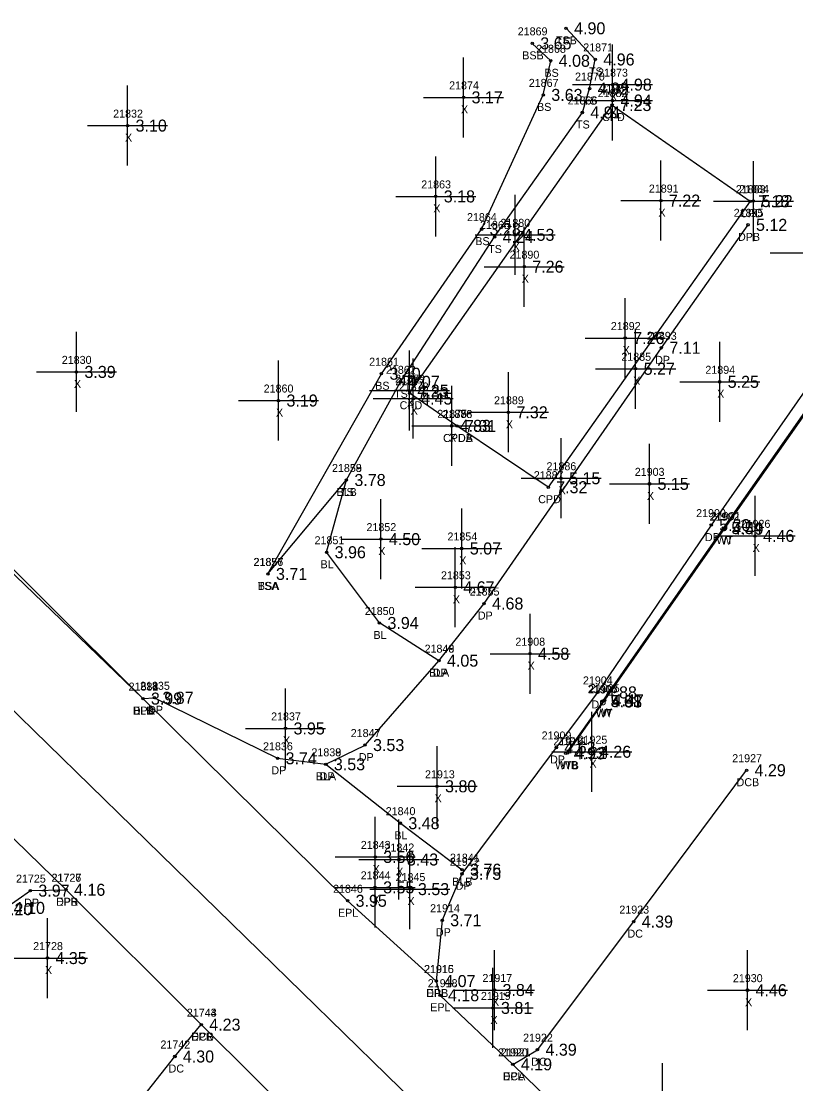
# Model space of a CAD drawing. Extents: x 2608745 to 2610333, y 641917 to 643463.
# Drawn here: x 2610174 to 2610270.8, y 642017.3 to 642150.1 of the extents above; entities that cross this region are included whole.
import ezdxf

# ---------------------------------------------------------------- set-up
doc = ezdxf.new("R2010")
doc.units = 0
for name, color, linetype in [('RD_DTM_BkLn1', 7, 'Continuous'), ('RD_DTM_BkLn2', 7, 'Continuous'), ('RD_DTM_BkLn_txCode', 7, 'Continuous'), ('RD_EX_BldgApp', 7, 'Continuous'), ('RD_EX_Conc', 7, 'Continuous'), ('RD_EX_Conc_txCode', 7, 'Continuous'), ('RD_EX_Driveway', 7, 'Continuous'), ('RD_EX_Driveway_txCode', 7, 'Continuous'), ('RD_EX_Misc', 7, 'Continuous'), ('RD_EX_Misc_txCode', 7, 'Continuous'), ('RD_EX_Road', 7, 'Continuous'), ('RD_EX_Road_txCode', 7, 'Continuous'), ('RD_EX_TX_Conc_ELEV', 7, 'Continuous'), ('RD_EX_TX_Driveway_ELEV', 7, 'Continuous'), ('RD_EX_TX_Misc_ELEV', 7, 'Continuous'), ('RD_EX_TX_Road_ELEV', 7, 'Continuous'), ('RD_SMD_Locator', 7, 'Continuous')]:
    doc.layers.add(name, color=color, linetype=linetype)

msp = doc.modelspace()

# ---------------------------------------------------------------- linework, layer by layer
at = {"layer": 'RD_DTM_BkLn1'}
for points in [[(2609568.4, 642647.43), (2609618.95, 642597.92), (2609693.89, 642525.38), (2609771.33, 642450.27), (2609850.26, 642373.69), (2609929.54, 642297.24), (2610000.01, 642230.49), (2610078.71, 642154.75), (2610156.09, 642080.44), (2610235.53, 642002.94), (2610263.59, 641975.77)], [(2609627.58, 642607.09), (2609630.23, 642605.37), (2609646.31, 642589.45), (2609703.16, 642535.02), (2609781.51, 642459.84), (2609859.44, 642383.51), (2609938.95, 642307.03), (2610008.76, 642239.49), (2610086.74, 642162.99), (2610105.31, 642145.89), (2610105.31, 642145.89), (2610140.26, 642113.1), (2610153.89, 642100.28), (2610164.72, 642089.82), (2610189.2, 642065.46)], [(2610226.2, 642070.2), (2610218.76, 642074.91), (2610212.16, 642083.75), (2610214.63, 642092.78)], [(2610212.06, 642057.25), (2610221.37, 642049.89), (2610229.08, 642044.08)]]:
    msp.add_lwpolyline(points, dxfattribs=at)
at = {"layer": 'RD_DTM_BkLn2'}
for points in [[(2610204.83, 642081.04), (2610214.63, 642092.78), (2610221.39, 642105.05), (2610233.15, 642123.15), (2610244.12, 642138.71), (2610245.03, 642141.7), (2610245.74, 642145.34), (2610242.09, 642149.23)], [(2610204.83, 642081.04), (2610219.01, 642106.06), (2610231.52, 642124.13), (2610239.24, 642140.91), (2610240.16, 642145.17), (2610237.86, 642147.35)], [(2610282.65, 642116.6), (2610261.73, 642086.77), (2610246.64, 642065.15), (2610246.68, 642065.1), (2610242.04, 642058.61)]]:
    msp.add_lwpolyline(points, dxfattribs=at)
at = {"layer": 'RD_EX_BldgApp'}
msp.add_lwpolyline([(2610282.97, 642116.74), (2610261.85, 642086.69), (2610246.9, 642065.25), (2610242.27, 642058.67)], dxfattribs=at)
at = {"layer": 'RD_EX_Conc'}
for points in [[(2610228.45, 642099.53), (2610222.53, 642103.62), (2610247.84, 642139.64), (2610265.09, 642127.62), (2610239.85, 642091.88), (2610228.45, 642099.53)], [(2610235.43, 642019.75), (2610238.51, 642021.58), (2610250.54, 642037.59), (2610264.64, 642056.51)], [(2610175.78, 641998.66), (2610183.75, 642008.74), (2610193.19, 642020.73), (2610196.49, 642024.71)]]:
    msp.add_lwpolyline(points, dxfattribs=at)
at = {"layer": 'RD_EX_Driveway'}
for points in [[(2610189.2, 642065.46), (2610190.63, 642065.56), (2610206.03, 642058), (2610212.06, 642057.25), (2610216.96, 642059.65), (2610226.2, 642070.2), (2610231.84, 642077.34), (2610253.99, 642109.3), (2610264.82, 642124.67)], [(2610280.77, 642116.6), (2610260.22, 642087.14), (2610246.03, 642066.23), (2610240.86, 642059.35), (2610229.07, 642043.56), (2610226.6, 642037.76), (2610225.86, 642030.16)], [(2610165.14, 642055.61), (2610164.87, 642054.53), (2610164.15, 642051.63), (2610160.61, 642047.27), (2610170.48, 642039.14), (2610172.05, 642039.3), (2610175.13, 642041.46), (2610179.59, 642041.57)]]:
    msp.add_lwpolyline(points, dxfattribs=at)
at = {"layer": 'RD_EX_Misc'}
for p, q in [((2610247.89, 642137.19), (2610247.89, 642147.19)), ((2610229.27, 642135.6), (2610229.27, 642145.6)), ((2610247.89, 642135.2), (2610247.89, 642145.2)), ((2610187.28, 642132.07), (2610187.28, 642142.07)), ((2610242.89, 642142.19), (2610252.89, 642142.19)), ((2610224.27, 642140.6), (2610234.27, 642140.6)), ((2610242.89, 642140.2), (2610252.89, 642140.2)), ((2610182.28, 642137.07), (2610192.28, 642137.07)), ((2610225.8, 642123.22), (2610225.8, 642133.22)), ((2610253.94, 642122.7), (2610253.94, 642132.7)), ((2610265.5, 642122.64), (2610265.5, 642132.64)), ((2610220.8, 642128.22), (2610230.8, 642128.22)), ((2610235.72, 642118.42), (2610235.72, 642128.42)), ((2610248.94, 642127.7), (2610258.94, 642127.7)), ((2610260.5, 642127.64), (2610270.5, 642127.64)), ((2610236.86, 642114.44), (2610236.86, 642124.44)), ((2610230.72, 642123.42), (2610240.72, 642123.42)), ((2610267.61, 642121.16), (2610277.61, 642121.16)), ((2610231.86, 642119.44), (2610241.86, 642119.44)), ((2610249.47, 642105.52), (2610249.47, 642115.52)), ((2610180.89, 642101.29), (2610180.89, 642111.29)), ((2610250.78, 642101.68), (2610250.78, 642111.68)), ((2610244.47, 642110.52), (2610254.47, 642110.52)), ((2610261.28, 642100.05), (2610261.28, 642110.05)), ((2610222.5, 642098.95), (2610222.5, 642108.95)), ((2610206.14, 642097.71), (2610206.14, 642107.71)), ((2610222.97, 642097.96), (2610222.97, 642107.96)), ((2610175.89, 642106.29), (2610185.89, 642106.29)), ((2610234.88, 642096.24), (2610234.88, 642106.24)), ((2610245.78, 642106.68), (2610255.78, 642106.68)), ((2610227.79, 642094.55), (2610227.79, 642104.55)), ((2610256.28, 642105.05), (2610266.28, 642105.05)), ((2610217.5, 642103.95), (2610227.5, 642103.95)), ((2610217.97, 642102.96), (2610227.97, 642102.96)), ((2610201.14, 642102.71), (2610211.14, 642102.71)), ((2610229.88, 642101.24), (2610239.88, 642101.24)), ((2610222.79, 642099.55), (2610232.79, 642099.55)), ((2610241.46, 642088), (2610241.46, 642098)), ((2610252.51, 642087.3), (2610252.51, 642097.3)), ((2610236.46, 642093), (2610246.46, 642093)), ((2610247.51, 642092.3), (2610257.51, 642092.3)), ((2610218.94, 642080.39), (2610218.94, 642090.39)), ((2610265.71, 642080.8), (2610265.71, 642090.8)), ((2610229.05, 642079.22), (2610229.05, 642089.22)), ((2610260.71, 642085.8), (2610270.71, 642085.8)), ((2610213.94, 642085.39), (2610223.94, 642085.39)), ((2610224.05, 642084.22), (2610234.05, 642084.22)), ((2610228.24, 642074.37), (2610228.24, 642084.37)), ((2610223.24, 642079.37), (2610233.24, 642079.37)), ((2610237.58, 642066.07), (2610237.58, 642076.07)), ((2610232.58, 642071.07), (2610242.58, 642071.07)), ((2610207.02, 642056.73), (2610207.02, 642066.73)), ((2610245.32, 642053.82), (2610245.32, 642063.82)), ((2610202.02, 642061.73), (2610212.02, 642061.73)), ((2610225.96, 642049.5), (2610225.96, 642059.5)), ((2610240.32, 642058.82), (2610250.32, 642058.82)), ((2610220.96, 642054.5), (2610230.96, 642054.5)), ((2610218.23, 642040.67), (2610218.23, 642050.67)), ((2610221.19, 642040.35), (2610221.19, 642050.35)), ((2610218.22, 642036.87), (2610218.22, 642046.87)), ((2610222.57, 642036.65), (2610222.57, 642046.65)), ((2610213.23, 642045.67), (2610223.23, 642045.67)), ((2610216.19, 642045.35), (2610226.19, 642045.35)), ((2610213.22, 642041.87), (2610223.22, 642041.87)), ((2610217.57, 642041.65), (2610227.57, 642041.65)), ((2610177.27, 642028.03), (2610177.27, 642038.03)), ((2610233.14, 642024.04), (2610233.14, 642034.04)), ((2610264.76, 642024.02), (2610264.76, 642034.02)), ((2610172.27, 642033.03), (2610182.27, 642033.03)), ((2610232.95, 642021.8), (2610232.95, 642031.8)), ((2610228.14, 642029.04), (2610238.14, 642029.04)), ((2610259.76, 642029.02), (2610269.76, 642029.02)), ((2610227.95, 642026.8), (2610237.95, 642026.8)), ((2610254.14, 642009.9), (2610254.14, 642019.9))]:
    msp.add_line(p, q, dxfattribs=at)
at = {"layer": 'RD_EX_Road'}
for points in [[(2609576.61, 642656.06), (2609590.88, 642642.24), (2609605.19, 642628.78), (2609627.58, 642607.09), (2609646.03, 642589.11), (2609702.18, 642534.04), (2609780.35, 642458.95), (2609858.79, 642382.83), (2609938.32, 642306.42), (2610008.62, 642239.32), (2610086.3, 642162.54), (2610164.18, 642089.49), (2610189.2, 642065.46), (2610214.78, 642040.19), (2610225.86, 642030.16), (2610226.32, 642028.39), (2610235.43, 642019.75), (2610260.23, 641995.63), (2610272.39, 641983.25)], [(2609841.8, 642365.54), (2609898.22, 642311.07), (2609921.04, 642289.43), (2609962.12, 642250.55), (2609969.04, 642244.08), (2609979.13, 642234.19), (2609992.4, 642221.66), (2610004.86, 642210.01), (2610027, 642188.8), (2610067.64, 642149.14), (2610070.8, 642146.19), (2610073.96, 642143.05), (2610116.51, 642103.01), (2610119.68, 642100.06), (2610135.09, 642085.92), (2610148.33, 642073.03), (2610165.14, 642055.61), (2610179.59, 642041.57), (2610196.49, 642024.71), (2610209.86, 642011.42), (2610228.39, 641994.06), (2610252.93, 641970.08), (2610256.35, 641966.74)]]:
    msp.add_lwpolyline(points, dxfattribs=at)
at = {"layer": 'RD_SMD_Locator'}
for centre in [(2610242.09, 642149.23), (2610237.86, 642147.35), (2610240.16, 642145.17), (2610245.74, 642145.34), (2610245.03, 642141.7), (2610247.89, 642142.19), (2610229.27, 642140.6), (2610239.24, 642140.91), (2610247.89, 642140.2), (2610244.12, 642138.71), (2610247.84, 642139.64), (2610187.28, 642137.07), (2610225.8, 642128.22), (2610253.94, 642127.7), (2610265.09, 642127.62), (2610265.5, 642127.64), (2610231.52, 642124.13), (2610264.82, 642124.67), (2610233.15, 642123.15), (2610235.72, 642123.42), (2610236.86, 642119.44), (2610249.47, 642110.52), (2610253.99, 642109.3), (2610250.78, 642106.68), (2610180.89, 642106.29), (2610219.01, 642106.06), (2610221.39, 642105.05), (2610261.28, 642105.05), (2610206.14, 642102.71), (2610222.5, 642103.95), (2610222.53, 642103.62), (2610222.97, 642102.96), (2610234.88, 642101.24), (2610227.79, 642099.55), (2610228.45, 642099.53), (2610228.45, 642099.53), (2610214.63, 642092.78), (2610214.63, 642092.78), (2610241.46, 642093), (2610252.51, 642092.3), (2610239.85, 642091.88), (2610260.22, 642087.14), (2610261.73, 642086.77), (2610218.94, 642085.39), (2610261.85, 642086.69), (2610265.71, 642085.8), (2610229.05, 642084.22), (2610212.16, 642083.75), (2610204.83, 642081.04), (2610204.83, 642081.04), (2610228.24, 642079.37), (2610231.84, 642077.34), (2610218.76, 642074.91), (2610237.58, 642071.07), (2610226.2, 642070.2), (2610226.2, 642070.2), (2610189.2, 642065.46), (2610189.2, 642065.46), (2610189.2, 642065.46), (2610190.63, 642065.56), (2610246.03, 642066.23), (2610246.64, 642065.15), (2610246.68, 642065.1), (2610246.9, 642065.25), (2610207.02, 642061.73), (2610216.96, 642059.65), (2610240.86, 642059.35), (2610245.32, 642058.82), (2610206.03, 642058), (2610242.04, 642058.61), (2610242.27, 642058.67), (2610212.06, 642057.25), (2610212.06, 642057.25), (2610264.64, 642056.51), (2610225.96, 642054.5), (2610221.37, 642049.89), (2610218.23, 642045.67), (2610221.19, 642045.35), (2610229.07, 642043.56), (2610229.08, 642044.08), (2610179.59, 642041.57), (2610179.59, 642041.57), (2610218.22, 642041.87), (2610222.57, 642041.65), (2610175.13, 642041.46), (2610214.78, 642040.19), (2610226.6, 642037.76), (2610250.54, 642037.59), (2610177.27, 642033.03), (2610225.86, 642030.16), (2610225.86, 642030.16), (2610226.32, 642028.39), (2610233.14, 642029.04), (2610264.76, 642029.02), (2610232.95, 642026.8), (2610196.49, 642024.71), (2610196.49, 642024.71), (2610193.19, 642020.73), (2610238.51, 642021.58), (2610235.43, 642019.75), (2610235.43, 642019.75)]:
    msp.add_circle(centre, 0.15, dxfattribs=at)

# ---------------------------------------------------------------- texts
at = {"layer": 'RD_DTM_BkLn_txCode'}
for s, p in [('21869', (2610236.04, 642148.35)), ('TSB', (2610240.82, 642147.23)), ('21868', (2610238.34, 642146.17)), ('21871', (2610244.23, 642146.34)), ('BSB', (2610236.61, 642145.35)), ('BS', (2610239.38, 642143.17)), ('TS', (2610244.95, 642143.34)), ('21867', (2610237.42, 642141.91)), ('21870', (2610243.2, 642142.7)), ('21866', (2610242.28, 642139.71)), ('TS', (2610244.24, 642139.7)), ('BS', (2610238.46, 642138.91)), ('TS', (2610243.33, 642136.71)), ('21864', (2610229.7, 642125.13)), ('21865', (2610231.33, 642124.15)), ('BS', (2610230.74, 642122.13)), ('TS', (2610232.35, 642121.15)), ('21861', (2610217.47, 642107.06)), ('21862', (2610219.57, 642106.05)), ('BS', (2610218.23, 642104.06)), ('TS', (2610220.59, 642103.05)), ('21858', (2610212.83, 642093.78)), ('21859', (2610212.83, 642093.78)), ('BLB', (2610213.4, 642090.78)), ('TS', (2610213.83, 642090.78)), ('21851', (2610210.65, 642084.75)), ('21856', (2610203.01, 642082.04)), ('21857', (2610203.04, 642082.04)), ('BL', (2610211.4, 642081.75)), ('TSA', (2610203.55, 642079.04)), ('BSA', (2610203.57, 642079.04)), ('21850', (2610216.93, 642075.91)), ('BL', (2610218.01, 642072.91)), ('21849', (2610224.4, 642071.2)), ('BLA', (2610224.95, 642068.2)), ('21582', (2610187.41, 642066.46)), ('BLB', (2610187.97, 642063.46)), ('21839', (2610210.26, 642058.25)), ('BLA', (2610210.81, 642055.25)), ('21840', (2610219.54, 642050.89)), ('BL', (2610220.62, 642047.89)), ('21841', (2610227.57, 642045.08)), ('BLB', (2610227.85, 642042.08))]:
    msp.add_text(s, height=1, dxfattribs=at).set_placement(p)
at = {"layer": 'RD_EX_Conc_txCode'}
for s, p in [('21882', (2610246.04, 642140.64)), ('CPD', (2610246.59, 642137.64)), ('21883', (2610263.3, 642128.62)), ('CPD', (2610263.84, 642125.62)), ('21877', (2610220.74, 642104.62)), ('CPD', (2610221.28, 642101.62)), ('21876', (2610226.63, 642100.53)), ('21888', (2610226.65, 642100.53)), ('CPDA', (2610226.71, 642097.53)), ('CPDB', (2610226.72, 642097.53)), ('21887', (2610238.05, 642092.88)), ('CPD', (2610238.6, 642089.88)), ('21927', (2610262.85, 642057.51)), ('DCB', (2610263.39, 642054.51)), ('21923', (2610248.74, 642038.59)), ('DC', (2610249.76, 642035.59)), ('21743', (2610194.69, 642025.71)), ('DCB', (2610195.24, 642022.71)), ('21922', (2610236.71, 642022.58)), ('21742', (2610191.39, 642021.73)), ('21921', (2610233.92, 642020.75)), ('DC', (2610237.73, 642019.58)), ('DC', (2610192.41, 642018.73)), ('DCA', (2610234.16, 642017.75))]:
    msp.add_text(s, height=1, dxfattribs=at).set_placement(p)
at = {"layer": 'RD_EX_Driveway_txCode'}
for s, p in [('21895', (2610263.03, 642125.67)), ('DPB', (2610263.57, 642122.67)), ('21893', (2610252.19, 642110.3)), ('DP', (2610253.21, 642107.3)), ('21900', (2610258.34, 642088.14)), ('DP', (2610259.44, 642085.14)), ('21855', (2610230.04, 642078.34)), ('DP', (2610231.06, 642075.34)), ('21848', (2610224.4, 642071.2)), ('DP', (2610225.42, 642068.2)), ('21834', (2610187.41, 642066.46)), ('21835', (2610188.84, 642066.56)), ('21904', (2610244.19, 642067.23)), ('DPA', (2610187.93, 642063.46)), ('DP', (2610189.85, 642063.56)), ('DP', (2610245.25, 642064.23)), ('21847', (2610215.17, 642060.65)), ('21909', (2610239.03, 642060.35)), ('21836', (2610204.21, 642059)), ('21838', (2610210.26, 642058.25)), ('DP', (2610216.18, 642057.65)), ('DP', (2610240.08, 642057.35)), ('DP', (2610205.25, 642056)), ('DP', (2610211.28, 642055.25)), ('21912', (2610227.55, 642044.56)), ('21725', (2610173.34, 642042.46)), ('21726', (2610177.77, 642042.57)), ('DP', (2610228.29, 642041.56)), ('DP', (2610174.35, 642039.46)), ('DPB', (2610178.34, 642039.57)), ('21914', (2610225.09, 642038.76)), ('DP', (2610225.82, 642035.76)), ('21915', (2610224.35, 642031.16)), ('DPB', (2610224.61, 642028.16))]:
    msp.add_text(s, height=1, dxfattribs=at).set_placement(p)
at = {"layer": 'RD_EX_Misc_txCode'}
for s, p in [('21873', (2610246.09, 642143.19)), ('21874', (2610227.47, 642141.6)), ('21881', (2610246.38, 642141.2)), ('X', (2610247.57, 642140.19)), ('21832', (2610185.48, 642138.07)), ('X', (2610228.95, 642138.6)), ('X', (2610247.58, 642138.2)), ('X', (2610186.96, 642135.07)), ('21863', (2610223.98, 642129.22)), ('21891', (2610252.43, 642128.7)), ('21884', (2610263.71, 642128.64)), ('X', (2610225.49, 642126.22)), ('X', (2610253.63, 642125.7)), ('21880', (2610233.88, 642124.42)), ('X', (2610265.19, 642125.64)), ('21890', (2610235.02, 642120.44)), ('X', (2610235.4, 642121.42)), ('X', (2610236.54, 642117.44)), ('21892', (2610247.68, 642111.52)), ('X', (2610249.16, 642108.52)), ('21830', (2610179.06, 642107.29)), ('21885', (2610248.99, 642107.68)), ('21894', (2610259.49, 642106.05)), ('21879', (2610220.71, 642104.95)), ('X', (2610250.47, 642104.68)), ('X', (2610180.58, 642104.29)), ('21860', (2610204.29, 642103.71)), ('21878', (2610221.18, 642103.96)), ('X', (2610222.19, 642101.95)), ('21889', (2610233.08, 642102.24)), ('X', (2610260.97, 642103.05)), ('X', (2610205.83, 642100.71)), ('X', (2610222.66, 642100.96)), ('21875', (2610225.99, 642100.55)), ('X', (2610234.56, 642099.24)), ('X', (2610227.48, 642097.55)), ('21886', (2610239.64, 642094)), ('21903', (2610250.67, 642093.3)), ('X', (2610241.14, 642091)), ('X', (2610252.19, 642090.3)), ('21902', (2610260.01, 642087.69)), ('21901', (2610260.18, 642087.77)), ('21852', (2610217.14, 642086.39)), ('21926', (2610263.9, 642086.8)), ('21854', (2610227.26, 642085.22)), ('WT', (2610260.87, 642084.77)), ('W', (2610261.48, 642084.69)), ('X', (2610218.62, 642083.39)), ('X', (2610265.4, 642083.8)), ('X', (2610228.74, 642082.22)), ('21853', (2610226.45, 642080.37)), ('X', (2610227.93, 642077.37)), ('21908', (2610235.75, 642072.07)), ('X', (2610237.27, 642069.07)), ('21906', (2610244.79, 642066.15)), ('21907', (2610244.85, 642066.1)), ('21905', (2610245.06, 642066.25)), ('21837', (2610205.22, 642062.73)), ('WT', (2610245.79, 642063.15)), ('WT', (2610245.82, 642063.1)), ('W', (2610246.53, 642063.25)), ('X', (2610206.7, 642059.73)), ('21910', (2610240.49, 642059.61)), ('21911', (2610241.04, 642059.67)), ('21925', (2610243.52, 642059.82)), ('WB', (2610241.42, 642056.67)), ('X', (2610245.01, 642056.82)), ('21913', (2610224.45, 642055.5)), ('WTB', (2610240.71, 642056.61)), ('X', (2610225.65, 642052.5)), ('21843', (2610216.43, 642046.67)), ('21842', (2610219.39, 642046.35)), ('X', (2610217.91, 642043.67)), ('21844', (2610216.42, 642042.87)), ('21845', (2610220.78, 642042.65)), ('X', (2610220.87, 642043.35)), ('X', (2610217.9, 642039.87)), ('X', (2610222.26, 642039.65)), ('21728', (2610175.48, 642034.03)), ('X', (2610176.96, 642031.03)), ('21917', (2610231.63, 642030.04)), ('21930', (2610262.93, 642030.02)), ('21919', (2610231.44, 642027.8)), ('X', (2610232.83, 642027.04)), ('X', (2610264.45, 642027.02)), ('X', (2610232.64, 642024.8))]:
    msp.add_text(s, height=1, dxfattribs=at).set_placement(p)
at = {"layer": 'RD_EX_Road_txCode'}
for s, p in [('21833', (2610187.41, 642066.46)), ('EPL', (2610188, 642063.46)), ('21727', (2610177.79, 642042.57)), ('21846', (2610212.96, 642041.19)), ('EPR', (2610178.36, 642039.57)), ('EPL', (2610213.58, 642038.19)), ('21916', (2610224.32, 642031.16)), ('21918', (2610224.8, 642029.39)), ('EPL', (2610224.65, 642028.16)), ('EPL', (2610225.11, 642026.39)), ('21744', (2610194.69, 642025.71)), ('EPR', (2610195.26, 642022.71)), ('21920', (2610233.59, 642020.75)), ('EPL', (2610234.22, 642017.75))]:
    msp.add_text(s, height=1, dxfattribs=at).set_placement(p)
at = {"layer": 'RD_EX_TX_Conc_ELEV'}
for s, p in [('7.23', (2610248.84, 642138.89)), ('7.18', (2610266.09, 642126.87)), ('7.33', (2610223.53, 642102.87)), ('7.31', (2610229.45, 642098.78)), ('7.31', (2610229.45, 642098.78)), ('7.32', (2610240.85, 642091.13)), ('4.29', (2610265.64, 642055.76)), ('4.10', (2610173.05, 642038.55)), ('4.39', (2610251.54, 642036.84)), ('4.23', (2610197.49, 642023.96)), ('4.39', (2610239.51, 642020.83)), ('4.30', (2610194.19, 642019.98)), ('4.19', (2610236.43, 642019))]:
    msp.add_text(s, height=1.5, dxfattribs=at).set_placement(p)
at = {"layer": 'RD_EX_TX_Driveway_ELEV'}
for s, p in [('5.12', (2610265.82, 642123.92)), ('7.11', (2610254.99, 642108.55)), ('5.30', (2610261.22, 642086.39)), ('4.68', (2610232.84, 642076.59)), ('4.05', (2610227.2, 642069.45)), ('4.88', (2610247.03, 642065.48)), ('3.99', (2610190.2, 642064.71)), ('3.87', (2610191.63, 642064.81)), ('3.53', (2610217.96, 642058.9)), ('4.62', (2610241.86, 642058.6)), ('3.74', (2610207.03, 642057.25)), ('3.53', (2610213.06, 642056.5)), ('3.75', (2610230.07, 642042.81)), ('3.97', (2610176.13, 642040.71)), ('4.16', (2610180.59, 642040.82)), ('4.20', (2610171.48, 642038.39)), ('4.10', (2610173.05, 642038.55)), ('3.71', (2610227.6, 642037.01)), ('4.07', (2610226.86, 642029.41))]:
    msp.add_text(s, height=1.5, dxfattribs=at).set_placement(p)
at = {"layer": 'RD_EX_TX_Misc_ELEV'}
for s, p in [('4.90', (2610243.09, 642148.48)), ('3.65', (2610238.86, 642146.6)), ('4.08', (2610241.16, 642144.42)), ('4.96', (2610246.74, 642144.59)), ('4.98', (2610248.89, 642141.44)), ('3.17', (2610230.27, 642139.85)), ('3.63', (2610240.24, 642140.16)), ('4.92', (2610246.03, 642140.95)), ('4.94', (2610248.89, 642139.45)), ('4.91', (2610245.12, 642137.96)), ('3.10', (2610188.28, 642136.32)), ('3.18', (2610226.8, 642127.47)), ('7.22', (2610254.94, 642126.95)), ('5.22', (2610266.5, 642126.89)), ('3.28', (2610232.52, 642123.38)), ('4.53', (2610236.72, 642122.67)), ('4.24', (2610234.15, 642122.4)), ('7.26', (2610237.86, 642118.69)), ('7.26', (2610250.47, 642109.77)), ('3.39', (2610181.89, 642105.54)), ('3.40', (2610220.01, 642105.31)), ('5.27', (2610251.78, 642105.93)), ('4.07', (2610222.39, 642104.3)), ('5.25', (2610262.28, 642104.3)), ('4.25', (2610223.5, 642103.2)), ('3.19', (2610207.14, 642101.96)), ('4.45', (2610223.97, 642102.21)), ('7.32', (2610235.88, 642100.49)), ('4.83', (2610228.79, 642098.8)), ('3.78', (2610215.63, 642092.03)), ('3.78', (2610215.63, 642092.03)), ('5.15', (2610242.46, 642092.25)), ('5.15', (2610253.51, 642091.55)), ('5.54', (2610262.73, 642086.02)), ('4.49', (2610262.85, 642085.94)), ('4.50', (2610219.94, 642084.64)), ('4.46', (2610266.71, 642085.05)), ('3.96', (2610213.16, 642083)), ('5.07', (2610230.05, 642083.47)), ('3.71', (2610205.83, 642080.29)), ('3.71', (2610205.83, 642080.29)), ('4.67', (2610229.24, 642078.62)), ('3.94', (2610219.76, 642074.16)), ('4.05', (2610227.2, 642069.45)), ('4.58', (2610238.58, 642070.32)), ('3.99', (2610190.2, 642064.71)), ('5.61', (2610247.64, 642064.4)), ('4.88', (2610247.68, 642064.35)), ('4.47', (2610247.9, 642064.5)), ('3.95', (2610208.02, 642060.98)), ('4.93', (2610243.04, 642057.86)), ('4.22', (2610243.27, 642057.92)), ('4.26', (2610246.32, 642058.07)), ('3.53', (2610213.06, 642056.5)), ('3.80', (2610226.96, 642053.75)), ('3.48', (2610222.37, 642049.14)), ('3.56', (2610219.23, 642044.92)), ('3.43', (2610222.19, 642044.6)), ('3.76', (2610230.08, 642043.33)), ('3.55', (2610219.22, 642041.12)), ('3.53', (2610223.57, 642040.9)), ('4.35', (2610178.27, 642032.28)), ('3.84', (2610234.14, 642028.29)), ('4.46', (2610265.76, 642028.27)), ('3.81', (2610233.95, 642026.05))]:
    msp.add_text(s, height=1.5, dxfattribs=at).set_placement(p)
at = {"layer": 'RD_EX_TX_Road_ELEV'}
for s, p in [('3.99', (2610190.2, 642064.71)), ('4.16', (2610180.59, 642040.82)), ('3.95', (2610215.78, 642039.44)), ('4.07', (2610226.86, 642029.41)), ('4.18', (2610227.32, 642027.64)), ('4.23', (2610197.49, 642023.96)), ('4.19', (2610236.43, 642019))]:
    msp.add_text(s, height=1.5, dxfattribs=at).set_placement(p)

doc.saveas('drawing.dxf')
